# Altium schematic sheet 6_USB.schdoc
size 530 x 154 mm
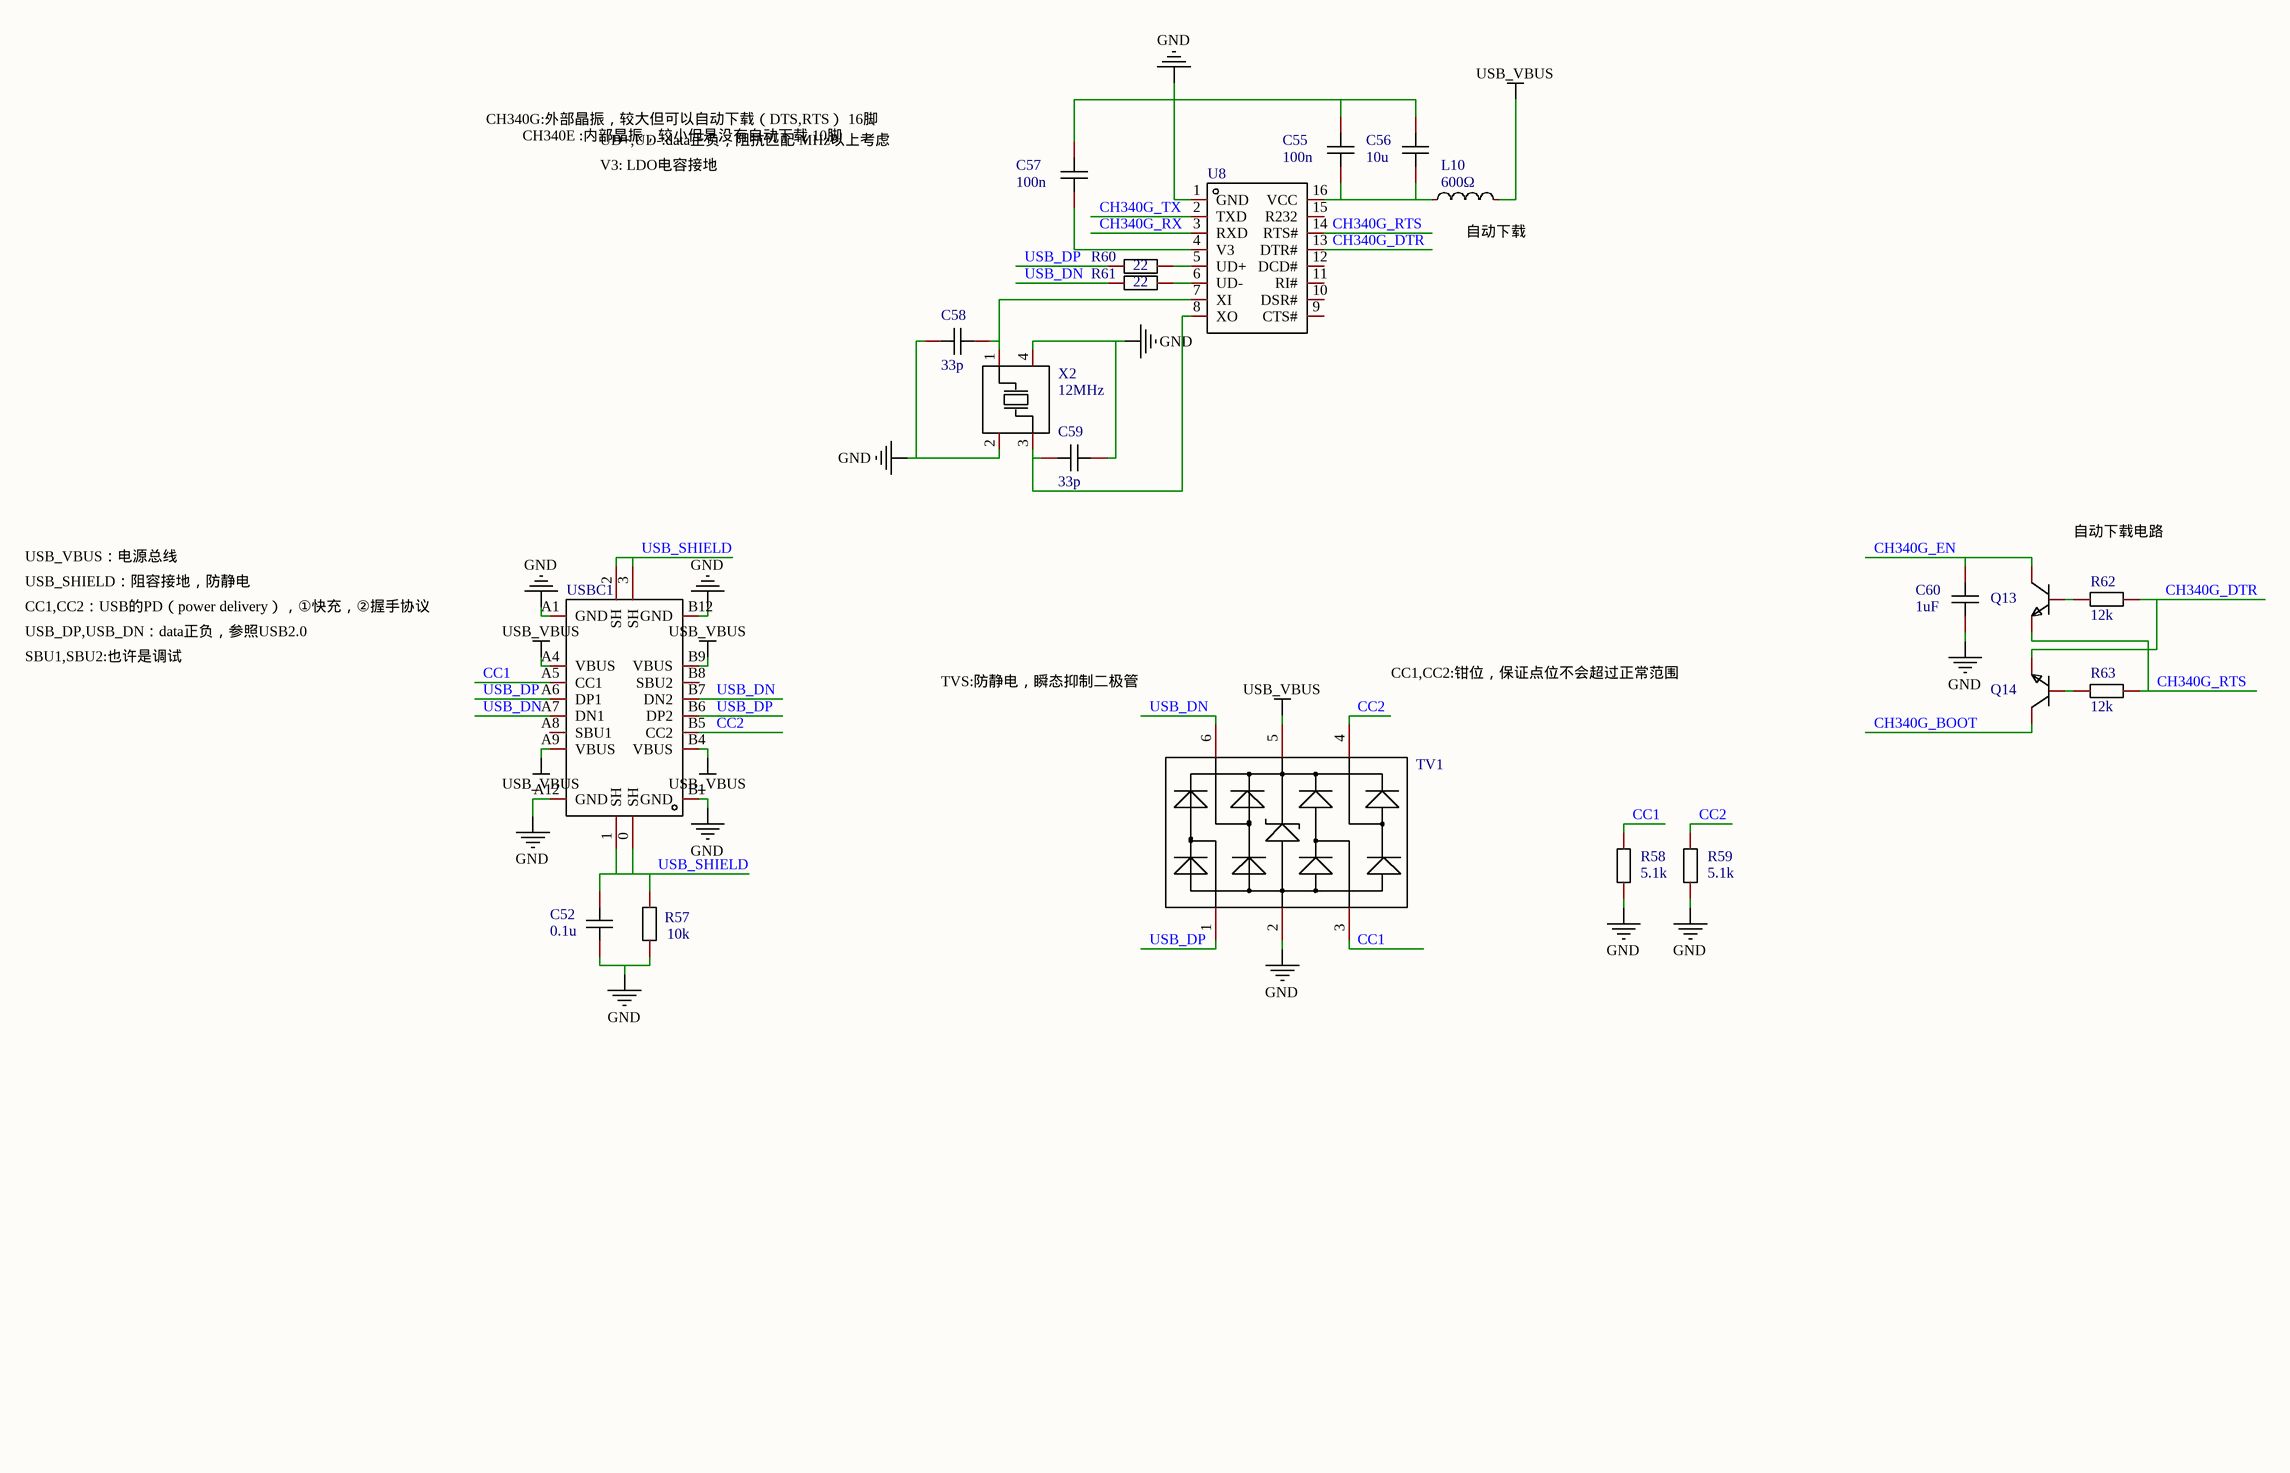
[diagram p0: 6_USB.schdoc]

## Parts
C52  0.1u  [C0603]
C55  100n  [C0603]
C56  10u  [C0603]
C57  100n  [C0603]
C58  33p  [C0603]
C59  33p  [C0603]
C60  1uF  [C0603]
L10  600Ω  [L0603]
Q13  SS8050  [SOT-23-3_L2.9-W1.3-P1.90-LS2.4-BR]  (value not drawn)
Q14  SS8050  [SOT-23-3_L2.9-W1.3-P1.90-LS2.4-BR]  (value not drawn)
R57  10k  [R0603]
R58  5.1k  [R0603]
R59  5.1k  [R0603]
R60  22  [R0603]
R61  22  [R0603]
R62  12k  [R0603]
R63  12k  [R0603]
TV1  SRV05-4-P-T7  [SOT-23-6_L2.9-W1.6-P0.95-LS2.8-BR]  (value not drawn)
U8  CH340G  [SOIC-16_L9.9-W3.9-P1.27-LS6.0-BL]  (value not drawn)
USBC1  TYPE-C-31-M-12  [USB-C_SMD-TYPE-C-31-M-12]  (value not drawn)
X2  12MHz  [OSC-SMD_4P-L3.2-W2.5-BL]

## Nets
GND: C52.1 C55.2 C56.2 C57.2 C58.1 C59.2 C60.2 R57.1 R58.1 R59.1 TV1.2 U8.1(GND) USBC1.A1(GND) USBC1.A12(GND) USBC1.B1(GND) USBC1.B12(GND) X2.2(GND) X2.4(GND)
USB_VBUS: L10.2 TV1.5 USBC1.A4(VBUS) USBC1.A9(VBUS) USBC1.B4(VBUS) USBC1.B9(VBUS)
CC1: R58.2 TV1.3 USBC1.A5(CC1)
CC2: R59.2 TV1.4 USBC1.B5(CC2)
CH340G_BOOT: Q14.3(C)
CH340G_DTR: Q14.2(E) R62.2 U8.13(DTR#)
CH340G_EN: C60.1 Q13.3(C)
CH340G_RTS: Q13.2(E) R63.2 U8.14(RTS#)
CH340G_RX: U8.3(RXD)
CH340G_TX: U8.2(TXD)
USB_DN: R61.1 TV1.6 USBC1.A7(DN1) USBC1.B7(DN2)
USB_DP: R60.1 TV1.1 USBC1.A6(DP1) USBC1.B6(DP2)
USB_SHIELD: C52.2 R57.2 USBC1.0(SH) USBC1.1(SH) USBC1.2(SH) USBC1.3(SH)
NetC55_1: C55.1 C56.1 L10.1 U8.16(VCC)
NetC57_1: C57.1 U8.4(V3)
NetC58_2: C58.2 U8.7(XI) X2.1(OSC1)
NetC59_1: C59.1 U8.8(XO) X2.3(OSC2)
NetQ13_1: Q13.1(B) R62.1
NetQ14_1: Q14.1(B) R63.1
NetR60_2: R60.2 U8.5(UD+)
NetR61_2: R61.2 U8.6(UD-)

Not connected (* = marked no-connect by the designer): U8 9(CTS#) 10(DSR#) 11(RI#) 12(DCD#) 15(R232); USBC1 A8(SBU1) B8(SBU2)

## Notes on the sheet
- CH340G:外部晶振，较大但可以自动下载（DTS,RTS） 16脚
  CH340E :内部晶振，较小但是没有自动下载 10脚
- UD+,UD-:data正负，阻抗匹配 MHz以上考虑
- V3: LDO电容接地
- (near L10) 自动下载
- USB_VBUS：电源总线
- 自动下载电路
- CC1,CC2：USB的PD（power delivery），①快充，②握手协议
- USB_SHIELD：阻容接地，防静电
- USB_DP,USB_DN：data正负，参照USB2.0
- SBU1,SBU2:也许是调试
- TVS:防静电，瞬态抑制二极管
- CC1,CC2:钳位，保证点位不会超过正常范围

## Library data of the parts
C52 C55-C60 = CAP_0603: Symbol: CapAcitance; Convert to PCB: yes
L10 = L_0603: Symbol: SDFL1608S100KTF; Add into BOM: yes
Q13 Q14 = SS8050_C2150: 晶体管类型:NPN;集射极击穿电压(Vceo):25V;集电极电流(Ic):1.5A;功率(Pd):300mW;直流电流增益(hFE@Ic,Vce):200@100mA,1V;; Manufacturer: CJ(江苏长电/长晶); Add into BOM: yes; Transistor Type: NPN; Collector-Emitter Breakdown Voltage (Vceo): 25V; Collector Current (Ic): 1.5A; Power Dissipation (Pd): 300mW; Collector Cut-Off Current (Icbo): 100nA; Collector-Emitter Saturation Voltage (VCE(sat)@Ic,Ib): 500mV@800mA,80mA; Transition Frequency (fT): 100MHz
R57 = AECR0603F1K50K9: Manufacturer: RESI(开步睿思）; Add into BOM: yes; Tolerance: ±1%; Power(Watts): 100mW; Temperature Coefficient: ±100ppm/℃; Overload Voltage (Max): 50V; Description: 电阻类型:厚膜电阻;阻值:1.5kΩ;精度:±1%;功率:100mW;温度系数:±100ppm/℃;最大工作电压:50V;工作温度范围:-55℃~+125℃;
R58-R63 = Res_0603: Symbol: 电阻; Convert to PCB: yes
TV1 = SRV05-4-P-T7_C85364: 反向截止电压(Vrwm):5V;击穿电压:6V;峰值脉冲电流(Ipp)@10/1000μs:1A@8/20us;最大钳位电压:12V;; Manufacturer: PROTEK; Add into BOM: yes; Reverse Stand-Off Voltage (Vrwm): 5V; Breakdown Voltage: 6V; Maximum Clamping Voltage: 12V
U8 = CH340G: 应用功能:Transceiver;接口协议:USB 2.0;数据速率:2Mbps;供电电压:3.3V；5V;; Manufacturer: WCH(南京沁恒); Add into BOM: yes; Protocol: USB 2.0; Data Rate: 2Mbps
USBC1 = TYPE-C-31-M-12: 连接器类型:Type-C;标准:-;公母:母座;触点数量:16;端口数量:1;安装方式:-;额定电流 - 电源:5A;触头材质:-;触头镀层:-;工作温度范围:-;焊接温度(最大值):-;; Manufacturer: 韩国韩荣; Add into BOM: yes; Connector Type: Type-C; Gender: 母座; Number of Contacts: 16; Number of Ports: 1; Current Rating - Power (Max): 5A
X2 = X322512MSB4SI: 晶振类型:贴片无源晶振;频率:12MHz;频率公差:±10ppm;频率稳定度:±30ppm;负载电容:20pF;工作温度:-40℃~+85℃;; Manufacturer: YXC(扬兴晶振); Add into BOM: yes; Crystal Type: 贴片无源晶振; Frequency Tolerance: ±10ppm; Frequency Stability: ±30ppm; Load Capacitance: 20pF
